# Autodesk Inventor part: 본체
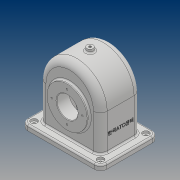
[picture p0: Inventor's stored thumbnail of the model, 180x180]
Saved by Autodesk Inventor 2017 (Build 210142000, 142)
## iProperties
Part Number: 본체
Material: 일반
Document SubType Name: Modeling
Designer: 20
Density: 1 g/cm^3
Appearance: 기본값
Mass: 404.475 g
Surface Area: 1182.21 cm^2
Volume: 404.475 cm^3
Author: 20
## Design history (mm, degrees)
sketch "스케치8"
  geometry: L1 (58, 0)-(58, -78); L2 (58, -78)-(-58, -78); L3 (-58, -78)-(-58, 0); A1 r 58 centre (0, 0) between (58, 0) and (-58, 0); 1 further point
  constraints: 6 end point, 2 coincident, 2 point on circle, 2 tangent, 2 vertical, 1 centre point, 1 horizontal
  dimensions: "d35" = 116 diameter of A1; "d44" = 78 distance from line of L2 point (0, 0)
extrude "돌출4" new body sketch "스케치8" stored distance "d38" = 77; taper "d39" = 0 deg
sketch "스케치11"
  geometry: L1 (-58, -78)-(58, -78) reference; C1 r 38 at (0, -13); 1 further point
  constraints: 1 centre point, 1 vertical alignment
  dimensions: "d45" = 76 diameter of C1; "d46" = 65 distance from line of L1 C1.centre
extrude "돌출5" join sketch "스케치11" distance "d47" = 5; taper "d48" = 0 deg
sketch "스케치12"
  geometry: L1 (58, 78)-(-58, 78) reference; C1 r 38 at (0, 13); 1 further point
  constraints: 1 centre point, 1 vertical alignment
  dimensions: "d49" = 76 diameter of C1; "d50" = 65 distance from line of L1 C1.centre
extrude "돌출6" join sketch "스케치12" distance "d51" = 10; taper "d52" = 0 deg
sketch "스케치14"
  geometry: L1 (52, 0)-(52, -78); L2 (-52, 0)-(-52, -78); L3 (52, -78)-(-52, -78); A1 r 52 centre (0, 0) between (52, 0) and (-52, 0); 1 further point
  constraints: 6 end point, 2 point on circle, 2 tangent, 2 vertical, 1 centre point, 1 coincident, 1 horizontal
  dimensions: "d62" = 104 diameter of A1; "d63" = 78 distance from line of L3 point (0, 0)
extrude "돌출7" cut sketch "스케치14" stored distance "d64" = 67; taper "d65" = 0 deg
node "작업 평면3"
sketch "스케치18"
  geometry: L1 (-52, -65)-(52, -65) reference; C1 r 28 at (0, 0); 1 further point
  constraints: 1 centre point, 1 vertical alignment
  dimensions: "d72" = 56 diameter of C1; "d73" = 65 distance from line of L1 C1.centre
extrude "돌출9" join sketch "스케치18" distance "d74" = 14; taper "d75" = 40 deg
sketch "스케치19"
  geometry: C1 r 38 at (0, 0) reference; C2 r 20 at (0, 0); 1 further point
  constraints: 1 centre point, 1 coincident
  dimensions: "d76" = 40 diameter of C2
extrude "돌출10" cut sketch "스케치19" stored distance "d77" = 67; taper "d78" = 0 deg
sketch "스케치20"
  geometry: L1 (-17, -93.5)-(133, -93.5); L2 (133, -93.5)-(133, 16.5); L3 (133, 16.5)-(-17, 16.5); L4 (-17, 16.5)-(-17, -93.5); L5 (-17, -93.5)-(133, 16.5); L6 (133, -93.5)-(-17, 16.5); L7 (0, 0)-(0, -77) reference; L8 (116, -77)-(0, -77) reference; L9 (116, 0)-(116, -77) reference; L10 (0, 0)-(116, 0) reference; 1 further point
  constraints: 12 end point, 2 midpoint, 2 parallel, 1 horizontal, 1 perpendicular
  dimensions: "d79" = 150 distance of L3.end L2.end; "d80" = 110 distance of L2.end L1.end
extrude "돌출11" join sketch "스케치20" distance "d81" = 10; taper "d82" = 0 deg
fillet "모깎기2" dims "d83" = 12
hole "구멍1" diameter "d86" = 5; stored, may be unused: countersink angle "d90" = 90 deg, drill point angle "d92" = 118 deg; dims "d84" = 10, "d85" = 10, "d87" = 6, "d88" = 12, "d89" = 4, "d91" = 8
hole "구멍2" diameter "d95" = 5; stored, may be unused: countersink angle "d99" = 90 deg, drill point angle "d101" = 118 deg; dims "d93" = 10, "d94" = 10, "d96" = 6, "d97" = 12, "d98" = 4, "d100" = 8
hole "구멍3" diameter "d104" = 5; stored, may be unused: countersink angle "d108" = 90 deg, drill point angle "d110" = 118 deg; dims "d102" = 10, "d103" = 10, "d105" = 6, "d106" = 12, "d107" = 4, "d109" = 8
hole "구멍4" diameter "d113" = 5; stored, may be unused: countersink angle "d117" = 90 deg, drill point angle "d119" = 118 deg; dims "d111" = 10, "d112" = 10, "d114" = 6, "d115" = 12, "d116" = 4, "d118" = 8
fillet "모깎기4" dims "d121" = 13
fillet "모깎기5" dims "d122" = 8
fillet "모깎기6" dims "d123" = 3
fillet "모깎기7" dims "d124" = 3
chamfer "모따기1" distance "d125" = 1; stored, may be unused: second distance "d126" = 2, angle "d127" = 45 deg
node "작업 평면4"
sketch "스케치22"
  geometry: L1 (138, -12)-(138, -98) reference; L2 (126, -110)-(0, -110) reference; C1 r 6 at (63, -55); 1 further point
  constraints: 1 centre point
  dimensions: "d131" = 12 diameter of C1; "d132" = 55 distance from line of L2 C1.centre; "d133" = 75 distance from line of L1 C1.centre
extrude "돌출12" join sketch "스케치22" stored distance "d134" = 10; taper "d135" = 5 deg
hole "구멍5" diameter "d138" = 4.459; stored, may be unused: countersink angle "d142" = 90 deg, drill point angle "d144" = 118 deg; dims "d136" = 10, "d137" = 10, "d139" = 10, "d140" = 12, "d141" = 4, "d143" = 12.8
sketch "스케치23"
  geometry: C1 r 38 at (0, 0) reference; 2 further points
  constraints: 1 vertical alignment
  dimensions: "d145" = 29 distance of C1.centre point (0, 29)
hole "구멍6" sketch "스케치23" at (0, 29) diameter "d146" = 3.242; stored, may be unused: countersink angle "d150" = 90 deg, drill point angle "d152" = 118 deg; dims "d147" = 8, "d148" = 12, "d149" = 4, "d151" = 10
sketch "스케치24"
  geometry: C1 r 21 at (0, 0) reference; 2 further points
  constraints: 1 vertical alignment
  dimensions: "d156" = 29 distance of C1.centre point (0, -29)
hole "구멍7" sketch "스케치24" at (0, -29) diameter "d157" = 3.242; stored, may be unused: countersink angle "d161" = 90 deg, drill point angle "d163" = 118 deg; dims "d158" = 8, "d159" = 12, "d160" = 4, "d162" = 10
fillet "모깎기8" dims "d167" = 3
sketch "스케치26"
  geometry: L1 (0, -13)-(65, -13) reference; L2 (78, -17.5)-(78, -29.5) reference; 2 further points
  constraints: 1 other
  dimensions: "d168" = 38.5 distance from line of L1 point (38, 25.5); "d169" = 40 distance from line of L2 point (38, 25.5)
feature "엠보싱1" sketch "스케치26" dims "d35" = 116, "d44" = 78, "d170" = 0.5, "d171" = 0
fillet "모깎기10" dims "d173" = 3
node "솔리드2"
pattern_circular "원형 패턴1" dims angle "d154" = 360 deg
pattern_circular "원형 패턴2" dims angle "d165" = 360 deg
other parameters: "d71" = -24, "d128" = -142
